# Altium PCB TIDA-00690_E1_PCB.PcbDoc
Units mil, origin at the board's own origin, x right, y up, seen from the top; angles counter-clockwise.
Board outline 2500 x 1700 mil, 2 copper layers (Top Layer, Bottom Layer), stack 62 mil thick; 46 components, 17 nets, 92 pads, 37 vias.
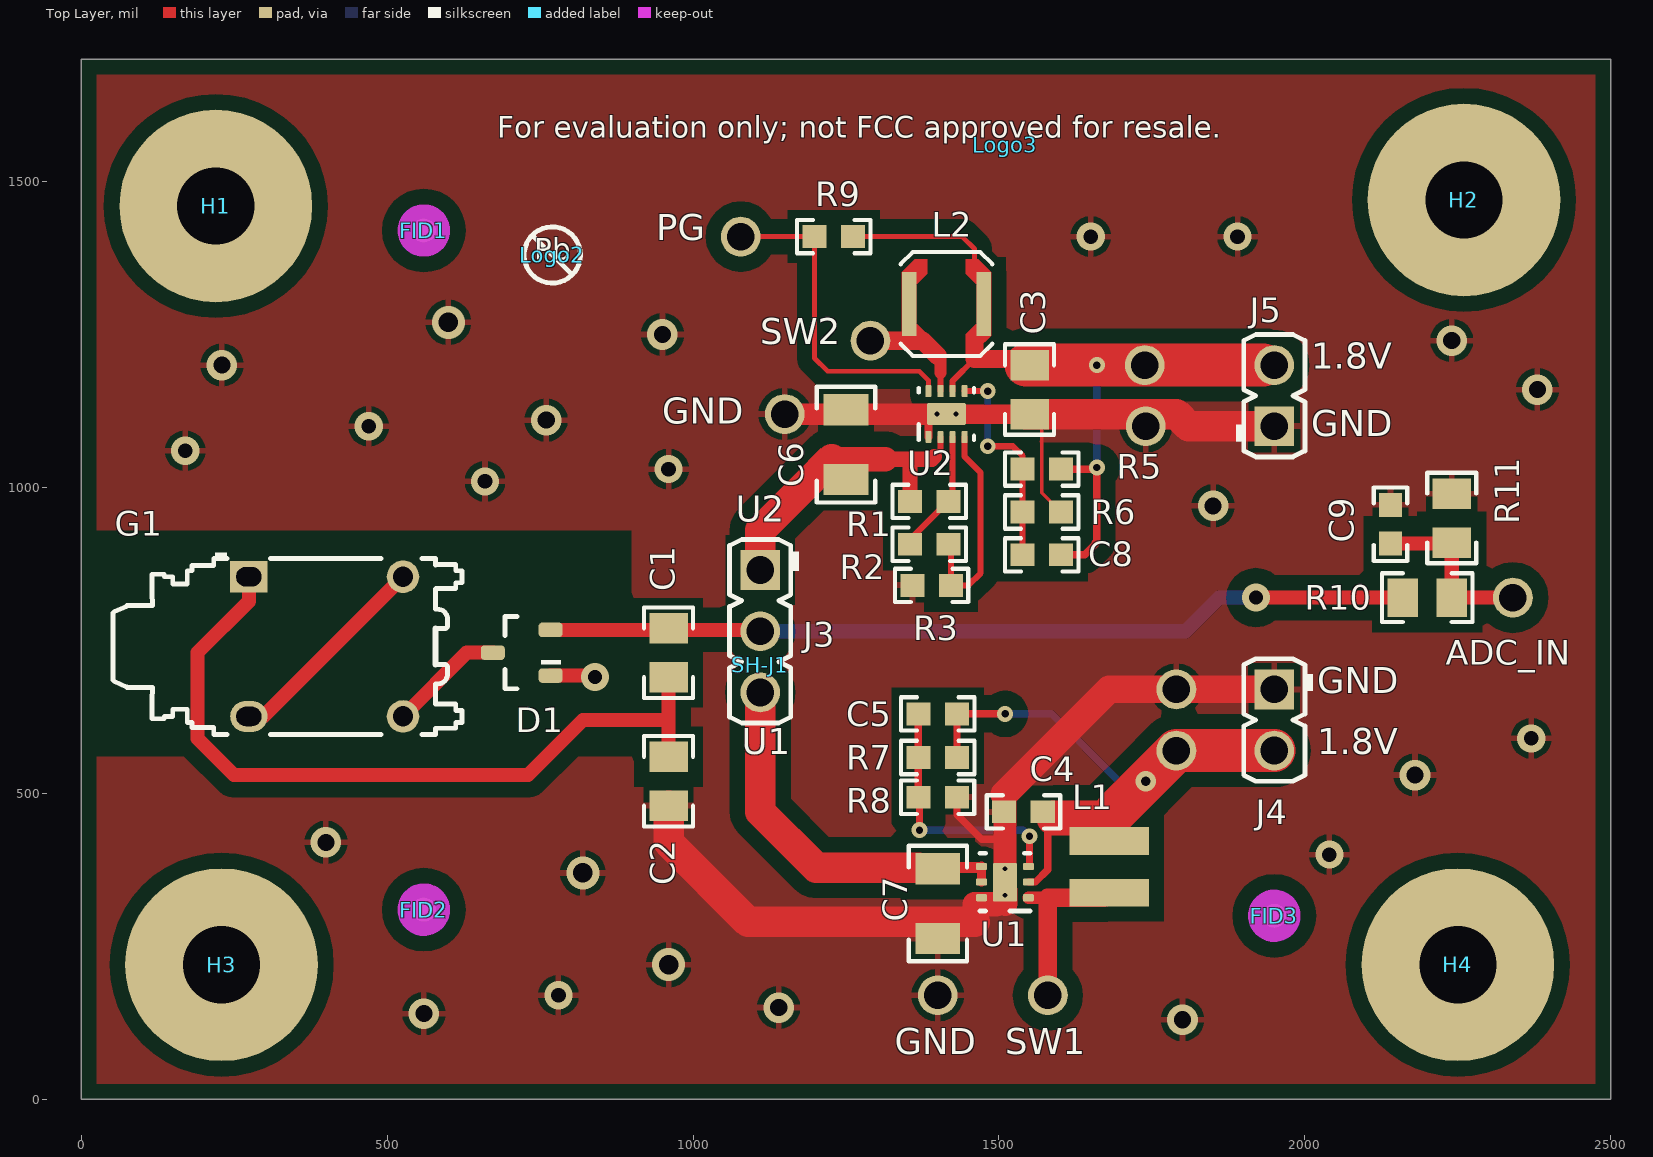
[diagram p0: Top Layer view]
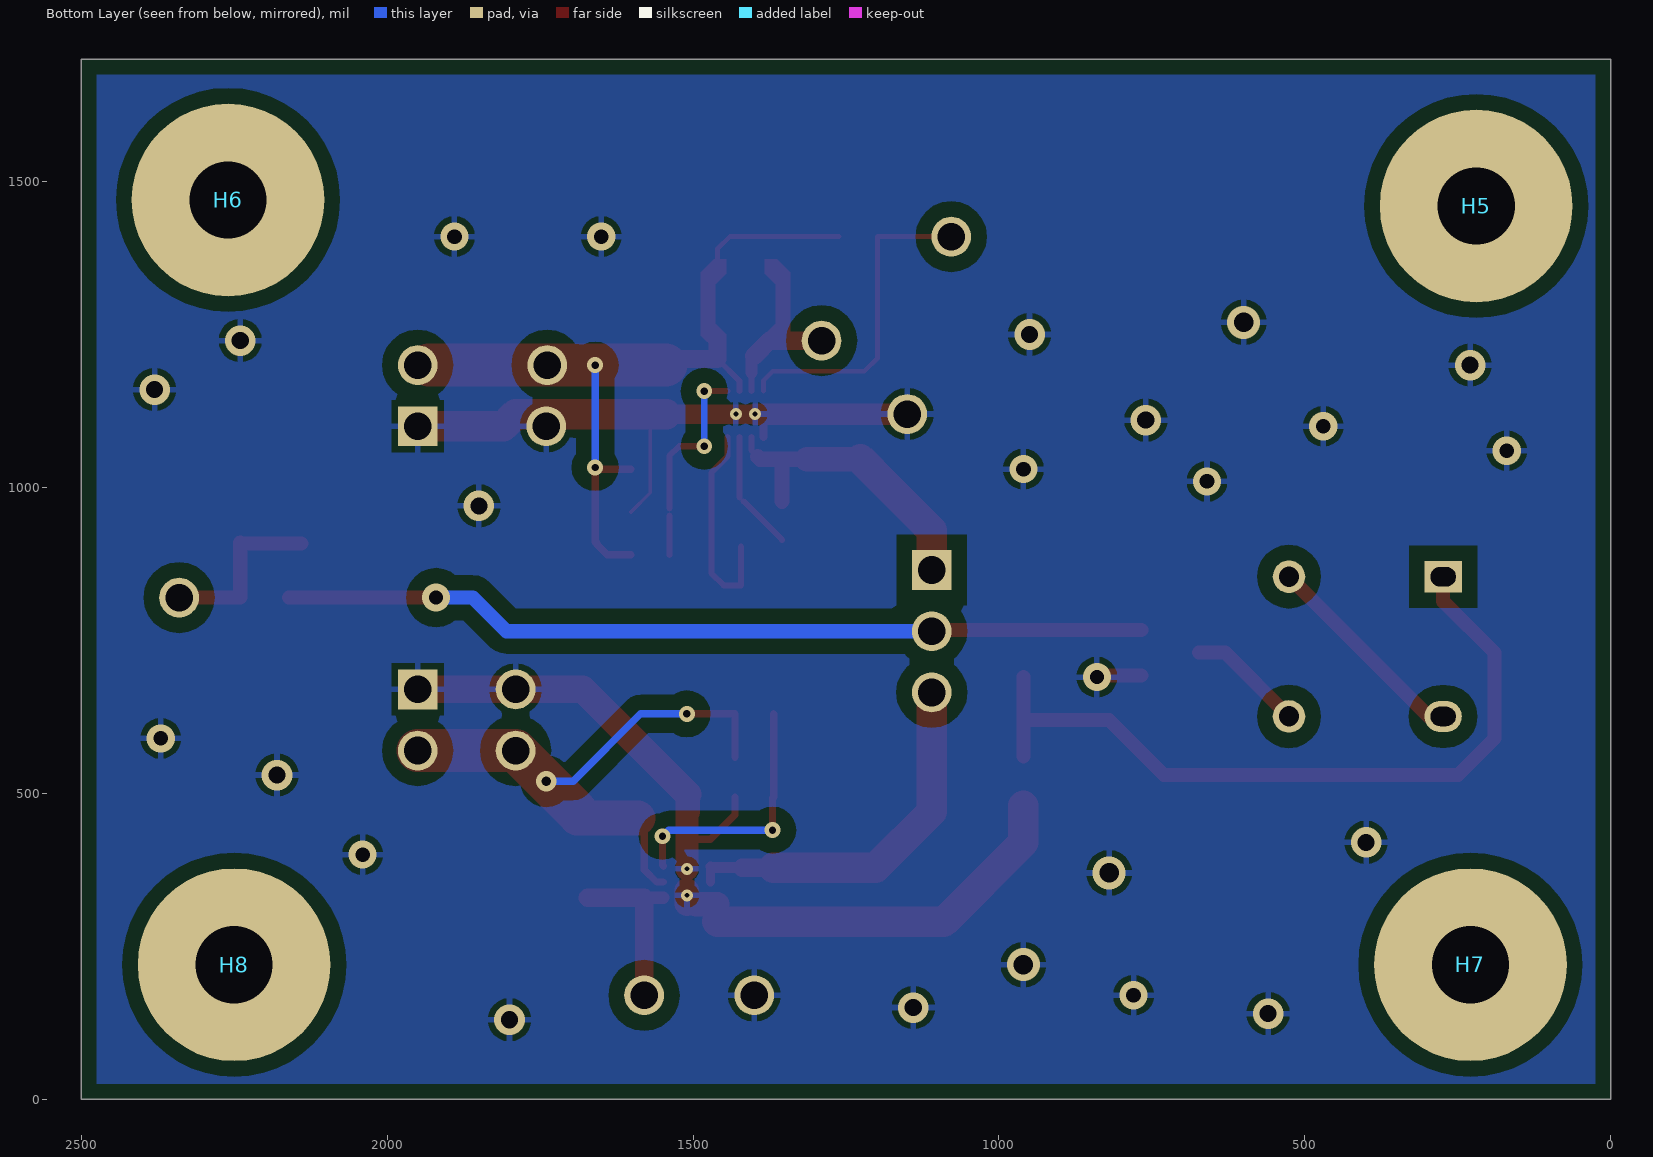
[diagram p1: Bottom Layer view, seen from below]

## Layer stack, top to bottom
Top Solder: solder mask 0.4, Solder Resist, Dk 3.5
Top Layer: signal copper 1.4
Dielectric1: core 59.2, FR-4, Dk 4.8
Bottom Layer: signal copper 1.4
Bottom Solder: solder mask 0.4, Solder Resist, Dk 3.5

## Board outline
0,0 2500,0 2500,1700 0,1700

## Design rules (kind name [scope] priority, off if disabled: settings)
AcuteAngle [All] p1: minimum=4.50000000000000E+0001 checktracksonly=FALSE
AssemblyTestPointUsage [All] p1: valid=2
BoardOutlineClearance BoardOutlineClearance_MountingHoles [OnCopper and InComponentClass('Mounting Holes')] p1: gap=40
BoardOutlineClearance BoardOutlineClearance_Poly [OnCopper and IsPoly] p2: gap=25
BoardOutlineClearance [OnCopper and Not InComponentClass('Logo') and not InComponentClass('FiducialMark') and not InRegion(1000,500,4000,800) and not InPoly] p3: gap=75
Clearance Clearance_Keepouts [((IsTrack Or IsArc) And Not InPoly) And IsFree and IsKeepOut vs ((IsTrack Or IsArc) And Not InPoly) And IsFree and IsKeepOut] p1: gap=0
Clearance Clearance_Poly [InPolygon] p2: gap=25
Clearance [All] p3: gap=7.87
ComponentClearance ComponentClearance_MountingHoles_FiducialMarks [InComponentClass('Mounting Holes') vs InComponentClass('FiducialMark')] p1: gap=50 collisioncheckmode=3 verticalgap=10 showdistances=FALSE
ComponentClearance ComponentClearance_Shunt [InComponentClass('Header') vs InComponentClass('Shunt')] p2: gap=0 collisioncheckmode=3 verticalgap=0 showdistances=FALSE
ComponentClearance ComponentClearance_Logo [InComponentClass('Logo')] p3: gap=50 collisioncheckmode=3 verticalgap=10 showdistances=FALSE
ComponentClearance ComponentClearance_ScrewToNut [(HasFootprint('NY PMS 440 0025 PH')) vs (HasFootprint('Keystone_1902C'))] p4: gap=5 collisioncheckmode=3 verticalgap=10 showdistances=FALSE
ComponentClearance ComponentClearance_MountingHoles [InComponentClass('Mounting Holes')] p5: gap=200 collisioncheckmode=3 verticalgap=100000 showdistances=FALSE
ComponentClearance ComponentClearance_SmallPassives [HasFootprint('0201*') or HasFootprint('0402*') or HasFootprint('0508') or HasFootprint('0603*') or HasFootprint('0612') or HasFootprint('0805*') or HasFootprint('0815*') or HasFootprint('0830*') or HasFootprint('1206*') or HasFootprint('1210*') or HasFootprint('1808*') or HasFootprint('1812*') or HasFootprint('1825*') or HasFootprint('2010*') or HasFootprint('2220*') or HasFootprint('2225*') or HasFootprint('2512*') or HasFootprint('2728*') or HasFootprint('3518*') vs HasFootprint('0201*') or HasFootprint('0402*') or HasFootprint('0508') or HasFootprint('0603*') or HasFootprint('0612') or HasFootprint('0805*') or HasFootprint('0815*') or HasFootprint('0830*') or HasFootprint('1206*') or HasFootprint('1210*') or HasFootprint('1808*') or HasFootprint('1812*') or HasFootprint('1825*') or HasFootprint('2010*') or HasFootprint('2220*') or HasFootprint('2225*') or HasFootprint('2512*') or HasFootprint('2728*') or HasFootprint('3518*')] p6: gap=14.96 collisioncheckmode=3 verticalgap=10 showdistances=FALSE
ComponentClearance ComponentClearance_THtoSMT [IsThruComponent vs IsSMTComponent] p7: gap=40 collisioncheckmode=3 verticalgap=30 showdistances=FALSE
ComponentClearance ComponentClearance_THtoTH [IsThruComponent vs IsThruComponent] p8: gap=30 collisioncheckmode=3 verticalgap=30 showdistances=FALSE
ComponentClearance [All] p9: gap=30 collisioncheckmode=3 verticalgap=10 showdistances=FALSE
DiffPairsRouting [All] p1: maxlimit=100 minlimit=10 mostfreqgap=10 toplayer_minwidth=15 toplayer_maxwidth=15 toplayer_prefwidth=15 bottomlayer_minwidth=15 bottomlayer_maxwidth=15 bottomlayer_prefwidth=15 maxuncoupledlength=1000
FabricationTestPointUsage TestPointUsage [All] p1: valid=2 allowmultiple=FALSE
FabricationTestpoint Testpoint [All] p1: side=3 testpointundercomponent=TRUE minsize=40 maxsize=100 preferedsize=60 minholesize=0 maxholesize=40 preferedholesize=32 testpointgrid=1 allowsidetop=TRUE allowsidebottom=TRUE usegrid=TRUE gridtolerance=0.01
FanoutControl Fanout_LCC [IsLCC] p1: bgadir=Out bgaviamode=Centered fanoutstyle=Auto fanoutdirection=Alternating viagrid=1 // Fanout_LCC (Default Rule)
FanoutControl Fanout_BGA [IsBGA] p2: bgadir=Out bgaviamode=Centered fanoutstyle=Auto fanoutdirection=Alternating viagrid=1 // Fanout_BGA (Default Rule)
FanoutControl Fanout_Default [All] p4: bgadir=Out bgaviamode=Centered fanoutstyle=Auto fanoutdirection=Alternating viagrid=1 // Fanout_Default (Default Rule)
FanoutControl Fanout_Small [(CompPinCount < 5)] p5: bgadir=Out bgaviamode=Centered fanoutstyle=Auto fanoutdirection=OutThenIn viagrid=1 // Fanout_Small (Default Rule)
HoleSize [All] p1: absolutevalues=TRUE maxlimit=251 minlimit=7.87 maxpercent=80.000 minpercent=20.000
MinimumAnnularRing MinimumAnnularRing_ThermalPadVias [IsVia and InAnyComponent] p1: minimumring=5.91
MinimumAnnularRing [All] p2: minimumring=6
MinimumSolderMaskSliver MinimumSolderMaskSliver_Logo [InComponentClass('Logo') vs InComponentClass('Logo')] p1: minsoldermaskwidth=0.7
MinimumSolderMaskSliver [All] p2: minsoldermaskwidth=3.94
PlaneConnect [All] p1: planeconnectstyle=Relief reliefexpansion=10 reliefentries=4 reliefconductorwidth=10 reliefairgap=10
PolygonConnect [All] p1: connectstyle=Relief reliefconductorwidth=10 reliefentries=4 polygonreliefangle="90 Angle" airgapwidth=10
RoutingVias ThermalPadVias [IsVia and InAnyComponent] p1: holewidth=7.87 width=19.68 viastyle="Through Hole" minholewidth=7.87 minwidth=19.68 maxholewidth=12.99 maxwidth=23.62
RoutingVias [All] p2: holewidth=16 width=34 viastyle="Through Hole" minholewidth=7.87 minwidth=26 maxholewidth=40 maxwidth=65
SilkToBoardRegionClearance [Not ((IsComment or IsDesignator) And (Hide <> 'False')) and not InRegion(1000,500,4000,800)] p1:
SilkToSilkClearance SilkToSilkClearance_Pb-FreeLogo [(HasFootprint('Pb-Free_Overlay_Medium') OR HasFootprint('Pb-Free_Overlay_Small')) vs (HasFootprint('Pb-Free_Overlay_Medium') OR HasFootprint('Pb-Free_Overlay_Small'))] p1: silktosilkclearance=0
SilkToSilkClearance [All] p2: silktosilkclearance=4
SilkToSolderMaskClearance SilkToComponentPadClearance [IsPad and InAnycomponent] p1: minsilkscreentomaskgap=2 clearancetoexposedcopper=TRUE
SilkToSolderMaskClearance "Silk to Solder Mask Opening" [All] p2: minsilkscreentomaskgap=3.8 clearancetoexposedcopper=FALSE
SolderMaskExpansion [All] p1: expansion=1.97
Width [All] p1: maxlimit=100 minlimit=6 preferedwidth=10 checkconnectedcopper=TRUE
15 further rules are at their usual default settings.

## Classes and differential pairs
component class TIDA-00690_E1_BlankSheet: ADC_IN C1 C2 C3 C4 C5 C6 C7 C8 C9 D1 G1 J3 J4 J5 L1 L2 R1 R2 R3 R5 R6 R7 R8 R9 R10 R11 SH-J1 U1 U2
component class Shunt: SH-J1
component class Header: J3 J4 J5
component class "Mounting Holes": H1 H2 H3 H4
component class TIDA-00690_E1_EVM_Hardware: FID1 FID2 FID3 H1 H2 H3 H4 H5 H6 H7 H8 Logo2 Logo3 ZZ2 ZZ3 ZZ4
component class FiducialMark: FID1 FID2 FID3
component class AssemblyNote: ZZ2 ZZ3 ZZ4

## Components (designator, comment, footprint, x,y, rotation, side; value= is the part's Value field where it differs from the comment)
ADC_IN "TESTPOINT" TP_H045P075 2340,820 r90 top
C1 "GRM21BR61E106MA73" 0805_HV 960,730 r270 top
C2 "GRM21BR61E106MA73" 0805_HV 960,520 r270 top
C3 "GRM21BR61C106KE15L" 0805_HV 1550,1160 r270 top
C4 "GRM188R60J475KE19D" 0603 1540,470 r180 top
C5 "GRM1885C1H220JA01D" 0603 1400,630 r180 top
C6 "GRM3195C1H102JA01D" 1206 1250,1070 r90 top
C7 "GRM3195C1H102JA01D" 1206 1400,320 r270 top
C8 "GRM1885C1H220JA01D" 0603 1570,890 r180 top
C9 "GRM188R71E104KA01D" 0603 2140,940 r90 top
D1 "DB3X316F0L" SOT-23 720,730 r180 top
FID1 "Fiducial" Fiducial10-20 560,1420 r0 top
FID2 "Fiducial" Fiducial10-20 560,310 r0 top
FID3 "Fiducial" Fiducial10-20 1950,300 r0 top
G1 "AFIG-0007" Cherry_AFIG-0007 400,740 r0 top
H1 "NY PMS 440 0025 PH" "NY PMS 440 0025 PH" 220,1460 r0 top locked
H2 "NY PMS 440 0025 PH" "NY PMS 440 0025 PH" 2260,1470 r0 top locked
H3 "NY PMS 440 0025 PH" "NY PMS 440 0025 PH" 229.47,220 r0 top locked
H4 "NY PMS 440 0025 PH" "NY PMS 440 0025 PH" 2250,220 r0 top locked
H5 "1902C" Keystone_1902C 220,1460 r180 bottom locked
H6 "1902C" Keystone_1902C 2260,1470 r180 bottom locked
H7 "1902C" Keystone_1902C 229.47,220 r180 bottom locked
H8 "1902C" Keystone_1902C 2250,220 r180 bottom locked
J3 "61300311121" WURTH_61300311121 1109.84,765.08 r270 top
J4 "61300211121" WURTH_61300211121 1950,620 r270 top
J5 "61300211121" WURTH_61300211121 1950,1150 r90 top
L1 "LQH3NPN220NG0" LQH3NP_G0 1680,380 r90 top
L2 "LPS3314-153MLB" LPS3314 1414.25,1300 r0 top
Logo2 "Pb-Free Symbol" Pb-Free_Overlay_Small 770,1380 r0 top
Logo3 "FCC disclaimer" FCC_disclaimer 1510,1560 r0 top
R1 "CRCW0603255KFKEA" 0603 1386,977.27 r180 top
R2 "CRCW0603200KFKEA" 0603 1386,907.27 r180 top
R3 "RC0603JR-0751KL" 0603 1390,840 r0 top
R5 "CRCW0603300KFKEA" 0603 1570,1030 r0 top
R6 "RC0603FR-07240KL" 0603 1570,960 r180 top
R7 "CRCW0603300KFKEA" 0603 1400,558.7 r0 top
R8 "RC0603FR-07240KL" 0603 1399.84,493.78 r180 top
R9 "CRCW0603100KJNEA" 0603 1230,1410 r0 top
R10 "CRCW08051M60JNEA" 0805_HV 2200,820 r180 top
R11 "CRCW08051M20JNEA" 0805_HV 2240,950 r270 top
SH-J1 "969102-0000-DA" SNT-100-BK-G 1110,710 r90 top
U1 "TPS62122DRVR" DRV0006A 1509.84,355.08 r180 top
U2 "TPS62125DSGR" DSG0008A 1414.25,1120 r90 top
ZZ2 "These assemblies are ESD sensitive, ESD precautions shall be observed." AssemblyNote 215,2539.11 r0 top
ZZ3 "These assemblies must be clean and free from flux and all contaminants. Use of no clean flux is not acceptable." AssemblyNote 215,2450.56 r0 top
ZZ4 "These assemblies must comply with workmanship standards IPC-A-610 Class 2, unless otherwise specified." AssemblyNote 215,2362 r0 top

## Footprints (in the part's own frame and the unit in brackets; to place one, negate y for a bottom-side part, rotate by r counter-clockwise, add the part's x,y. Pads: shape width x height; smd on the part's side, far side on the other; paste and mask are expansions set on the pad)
0603 [mm] "0603 from SM-752 data"
  rect 1x0.95 smd: 1(-0.8,0) 2(0.8,0)
  silkscreen extent -1.52,-0.69 1.52,0.69, body extent -0.87,-0.47 0.87,0.47, height 1
0805_HV [mil] "0805 with 30mil clearance between pads"
  rect 50x63 smd: 1(-40,0) 2(40,0)
  silkscreen extent -74,-40 74,40, body extent -43,-29 43,29, height 57
1206 [mm] "1206 from SM-752 data"
  rect 1.3x1.85 smd: 1(-1.45,0) 2(1.45,0)
  silkscreen extent -2.4,-1.21 2.4,1.21, body extent -1.7,-0.9 1.7,0.9, height 1.35
AssemblyNote [mil] "Assembly Note"
Cherry_AFIG-0007 [mm] "AC generator, Through-hole mount"
  rect 1.55x1.3 hole 0.8 slot 1.05 at 0 deg: 1(-3.2,2.9)
  oval 1.55x1.3 hole 0.8 slot 1.05 at 0 deg: 2(-3.2,-2.9)
  round 1.35 hole 0.85: 3(3.2,-2.9) 4(3.2,2.9)
  silkscreen extent -8.84,-3.65 5.65,3.9, body extent -8.84,-3.65 5.64,3.65, height 18.51
DRV0006A [mm] "SON, 6-Leads, Body 2x2mm, Pitch 0.65mm, Thermal Pad 1.6x1mm, TI Recommended"
  rrect33% 0.45x0.3 smd: 1(-0.975,0.65) 2(-0.975,0) 3(-0.975,-0.65) 4(0.975,-0.65) 5(0.975,0) 6(0.975,0.65)
  rrect14% 1x0.7 on Top Paste: 7(0,0.45) 7(0,-0.45)
  rrect10% 1x1.6 smd paste-0.5: 7(0,0)
  silkscreen extent -1.05,-1.2 1.05,1.2, body extent -1.05,-1.05 1.05,1.05, height 0.81
DSG0008A [mm] "SON, 8-Leads, Body 2x2mm, Pitch 0.5mm, Thermal Pad 1.6x0.9mm, TI Recommended"
  rrect40% 0.5x0.25 smd: 1(-0.95,0.75) 2(-0.95,0.25) 3(-0.95,-0.25) 4(-0.95,-0.75) 5(0.95,-0.75) 6(0.95,-0.25) 7(0.95,0.25) 8(0.95,0.75)
  rrect11% 0.9x1.6 smd paste-0.45: 9(0,0)
  silkscreen extent -1.07,-1.15 1.07,1.15, body extent -1.05,-1.05 1.05,1.05, height 0.8
FCC_disclaimer [mil]
Fiducial10-20 [mm]
  round 1 smd mask+0.5: 1(0,0)
  Top Layer keep-out circle w1.178: c0,0 r0.5
Keystone_1902C [mil] "Hex Standoff, 4-40 threaded, nylon"
  body extent -145,-126 146,126, height 501
LPS3314 [mm] "Coilcraft recommended land pattern, Document 541-2 Revised 08/05/09"
  rect 0.6x2.65 smd: 1(-1.55,0) 2(1.55,0)
  Top Layer region: 0.8,-1.85 0.8,-1.25 1.25,-0.8 1.25,0.8 0.8,1.25 0.8,1.85 1.325,1.85 1.85,1.325 1.85,-1.325 1.325,-1.85
  Top Layer region: -1.325,-1.85 -1.85,-1.325 -1.85,1.325 -1.325,1.85 -0.8,1.85 -0.8,1.25 -1.25,0.8 -1.25,-0.8 -0.8,-1.25 -0.8,-1.85
  silkscreen extent -1.91,-2.16 1.91,2.16, body extent -1.7,-1.7 1.7,1.7, height 1.42
LQH3NP_G0 [mm] "MURATA"
  rect 1.15x3.3 smd: 1(-1.075,0) 2(1.075,0)
  body extent -1.6,-1.6 1.6,1.6, height 1.01
"NY PMS 440 0025 PH" [mm] "4-40 nylon screw and mounting hole"
  round 8 hole 3.2: 1(0,0)
  body extent -3.3,-3.3 3.3,3.3, height 2.69
Pb-Free_Overlay_Small [mil]
  silkscreen extent -46,-46 46,46
SNT-100-BK-G [mil] "Samtec STEP model"
  round 1 on Mech3: 0(0,0)
  body extent -100,-50 100,50, height 344
SOT-23 [mm] "SOT23, 3-Leads, Body 2.9x1.3mm, Pitch 0.95mm, Lead Span 2.5mm, IPC Medium Density"
  rrect50% 1x0.6 smd: 1(-1.2,0.95) 2(-1.2,-0.95) 3(1.2,0)
  silkscreen extent -1.63,-1.5 0.7,1.5, body extent -1.16,-1.45 1.21,1.45, height 1
TP_H045P075 [mil] "TP_H0.45P0.75"
  round 65 hole 45: 1(0,0)
WURTH_61300211121 [mm] "Header, 2.54mm, 2x1, TH"
  rect 1.65x1.65 hole 1.15: 1(-1.27,0)
  round 1.65 hole 1.15: 2(1.27,0)
  silkscreen extent -2.54,-1.27 2.54,1.6, body extent -2.54,-1.27 2.54,1.27, height 8.54
WURTH_61300311121 [mm] "Header, 2.54mm, 3x1, TH"
  rect 1.65x1.65 hole 1.15: 1(-2.54,0)
  round 1.65 hole 1.15: 2(0,0) 3(2.54,0)
  silkscreen extent -3.81,-1.27 3.81,1.6, body extent -3.81,-1.27 3.81,1.27, height 8.54

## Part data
ADC_IN: library part TP_H0.45P0.75, "Testpoint"
C1 C2: "CAP, CERM, 10 µF, 25 V, +/- 20%, X5R, 0805"
C3: "CAP, CERM, 10 µF, 16 V, +/- 10%, X5R, 0805"
C4: "CAP, CERM, 4.7 µF, 6.3 V, +/- 10%, X5R, 0603"
C5 C8: "CAP, CERM, 22 pF, 50 V, +/- 5%, C0G/NP0, 0603"
C6 C7: "CAP, CERM, 1000 pF, 50 V, +/- 5%, C0G/NP0, 1206"
C9: "CAP, CERM, 0.1 µF, 25 V, +/- 10%, X7R, 0603"
D1: "Diode, Schottky, 30 V, 0.1 A, SOT-23"
FID1 FID2 FID3: "Fiducial mark.  There is nothing to buy or mount."
G1: "AC generator, Through-hole mount"
H1 H2 H3 H4: "Machine Screw, Round, #4-40 x 1/4, Nylon, Philips panhead"
H5 H6 H7 H8: "Standoff, Hex, 0.5\"L #4-40 Nylon"
J3: "Header, 2.54 mm, 3x1, Gold, TH"
J4 J5: "Header, 2.54 mm, 2x1, Gold, TH"
L1: "Inductor, Wirewound, Ferrite, 22 µH, 0.34 A, 1.1 ohm, SMD"
L2: "Inductor, Shielded Drum Core, Ferrite, 15 µH, 0.59 A, 0.44 ohm, SMD"
Logo2: library part Pb-Free
Logo3: library part FCC_disclaimer, "FCC_disclaimer"
R1: "RES, 255 k, 1%, 0.1 W, 0603"
R2: "RES, 200 k, 1%, 0.1 W, 0603"
R3: "RES, 51 k, 5%, 0.1 W, 0603"
R5 R7: "RES, 300 k, 1%, 0.1 W, 0603"
R6 R8: "RES, 240 k, 1%, 0.1 W, 0603"
R9: "RES, 100 k, 5%, 0.1 W, 0603"
R10: "RES, 1.6 M, 5%, 0.125 W, 0805"
R11: "RES, 1.2 M, 5%, 0.125 W, 0805"
SH-J1: "Shunt, 100mil, Gold plated, Black"
U1: "Buck Step Down Regulator with 2 to 15 V Input and 1.2 to 5.5 V Output, -40 to 85 degC, 6-Pin SON (DRV), Green (RoHS & no Sb/Br)"
U2: "3V-17V, 300mA Step Down Converter With Adjustable Enable Threshold And Hysteresis, DSG0008A"
ZZ2 ZZ3 ZZ4: library part AssemblyNote

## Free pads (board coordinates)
  round 65 hole 45: 3(1400,170) 4(1290,1240) 5(1150,1120) 6(1738.37,1200) 7(1740,1100) 8(1790,670) 9(1790,570) 10(1078,1410) 12(1580,170)

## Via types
v1: diameter 50, hole 28, Top Layer to Bottom Layer, 11 vias
v2: diameter 46, hole 24, Top Layer to Bottom Layer, 9 vias
v3: diameter 26, hole 12, Top Layer to Bottom Layer, 7 vias
v4: diameter 19.68, hole 7.87, Top Layer to Bottom Layer, 4 vias
v5: diameter 54, hole 32, Top Layer to Bottom Layer, 3 vias
v6: diameter 46, hole 23, Top Layer to Bottom Layer, 2 vias
v7: diameter 34, hole 16, Top Layer to Bottom Layer, 1 vias

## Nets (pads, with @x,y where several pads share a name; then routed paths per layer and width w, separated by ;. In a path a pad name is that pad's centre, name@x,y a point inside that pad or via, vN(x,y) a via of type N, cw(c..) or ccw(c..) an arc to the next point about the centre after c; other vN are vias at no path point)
GND: C2.2 C3.2 C4.2 C6.2 C7.2 C9.2 D1.1 J4.1 J5.1 pad.3 pad.5 pad.7 pad.8 R3.1 R6.1 R8.1 R11.1 U1.6 U1.7@1509.84,355.08 U2.1 U2.9 | length 2465
  Top Layer w6: C3.2@1570,1120 1570,991.5 R6.1
  Top Layer w12: R8.1 1431.34,465.08 1471.34,425.08 1509.84,425.08
  Top Layer w13: U2.1 U2.9@1384.72,1105.37
  Top Layer w23: D1.1 v6@837.4,692.6
  Top Layer w32: v4(1398.5,1120) U2.9 C3.2@1544.25,1120
  Top Layer w35: pad.5@1180,1120 v4(1398.5,1120)
  Top Layer w38: v4(1509.84,376.73) 1509.84,425.08 C4.2@1509.84,466.57
  Top Layer w40: 1460,319.12 1495.54,319.12 ; C4.2 1508.5,498.5 ; 1510,320 U1.7@1510,341.65
  Top Layer w45: 1508.5,498.5 1680,670 J4.1@1940,670
  Top Layer w50: C2.2 960,420 1090,290 1460,290 ; C3.2@1544.25,1120 1790,1120 1810,1100 J5.1@1955,1100
  other v1: 1800,130 560,140 1140,150 400,420 2180,530 1850,970 760,1110 2380,1160 230,1200 2240,1240 950,1250
  other v2: 780,170 2040,400 2370,590 660,1010 960,1030 170,1060 470,1100 1650,1410 1890,1410
  other v4: 1509.84,333.43 1430,1120
  other v5: 960,220 820,370 600,1270
  other v6: 840,690
NetADC_IN_1: ADC_IN.1 C9.1 R10.1 R11.2 | length 288.5
  Top Layer w23: C9.1 R11.2@2238.5,908.5 ; R11.2 R10.1 ADC_IN.1
NetC1_1: C1.1 D1.2 J3.2 R10.2 | length 1413.2
  Top Layer w23: D1.2 J3.2@1107.52,767.4 ; v6(1920,820) R10.2
  Bottom Layer w23: J3.2 1805.08,765.08 1860,820 v6(1920,820)
NetC1_2: C1.2 C2.1 G1.1 | length 1261.1
  Top Layer w23: G1.1 274.02,814.02 190,730 190,590 250,530 730,530 820,620 960,620 ; C2.1 960,620 ; C1.2 960,620
NetC5_2: C5.2 R7.1 R8.2 U1.3 | length 425
  Top Layer w12: C5.2 1368.35,629.84 R8.2 1370,492.13 v3(1370,440) ; U1.3 1550,382.44 v3(1550,430)
  Bottom Layer w12: v3(1370,440) 1540,440 v3(1550,430)
NetC8_2: C8.2 R5.1 R6.2 U2.5 | length 341.3
  Top Layer w10: U2.5 v3(1481.65,1157.4) ; v3(1481.65,1067.4) 1522.6,1067.4 1538.5,1051.5 R5.1 R6.2@1538.5,965.75 ; C8.2 R6.2@1538.5,954.25
  Bottom Layer w10: v3(1481.65,1067.4) v3(1481.65,1157.4)
NetD1_3: D1.3 G1.3 | length 189.9
  Top Layer w23: G1.3 630.16,730 D1.3
NetG1_2: G1.2 G1.4 | length 346.6
  Top Layer w23: G1.2 297.64,625.83 G1.4
NetL1_1: L1.1 pad.12 U1.1 | length 283.1
  Top Layer w20: U1.1 1580,329.49
  Top Layer w30: pad.12 1580,329.49 L1.1@1671.81,329.49
NetL2_1: L2.1 pad.4 U2.7 | length 171.6
  Top Layer w10: U2.7 1404.41,1185.59
  Top Layer w20: 1404.41,1187.51 1404.41,1210.59
  Top Layer w30: pad.4 1375,1240 1400,1215
NetR1_1: R1.1 R2.2 U2.3 | length 187.8
  Top Layer w10: R2.2@1354.5,914.27 R1.1 ; R1.1@1424.09,983.86 U2.3
NetR2_1: R2.1 R3.2 U2.4 | length 353.5
  Top Layer w10: R2.1@1421.5,903.27 R3.2 1450,840 1470,860 1470,1024.25 1443.78,1050.47 U2.4
NetR9_1: pad.10 R9.1 U2.8 | length 538.1
  Top Layer w8: pad.10 R9.1 1198.5,1211.5 1220,1190 1370,1190 1384.72,1175.28 U2.8
VIN1: C7.1 J3.3 U1.4 U1.5 | length 620.8
  Top Layer w14: U1.5 U1.4
  Top Layer w16: U1.4@1469.49,378.7 U1.4
  Top Layer w18: C7.1@1419.84,378.7 U1.4@1469.49,378.7
  Top Layer w30: C7.1@1368.7,378.7 C7.1@1419.84,378.7
  Top Layer w50: J3.3 1109.84,470.16 1201.3,378.7 C7.1@1368.7,378.7
VIN2: C6.1 J3.1 R1.2 U2.2 | length 502.8
  Top Layer w10: 1394.25,1050 1404.41,1060.16 U2.2
  Top Layer w25: 1314.25,1046.38 1390.63,1046.38 1394.25,1050 ; R1.2 1354.5,1044.32
  Top Layer w40: 1226.38,1046.38 1314.25,1046.38
  Top Layer w50: J3.1 1109.84,929.84 1185.08,1005.08 1226.38,1046.38
VOUT1: C4.1 C5.1 J4.2 L1.2 pad.9 R7.2 U1.2 | length 948.3
  Top Layer w12: R7.2@1431.34,558.7 1431.34,630 v3(1510,630) ; U1.2 1559.84,355.08 1579.84,375.08 C4.1@1579.84,456.57
  Top Layer w57: C4.1@1590,460 1690,460
  Top Layer w70: 1690,470 v7(1740,520) pad.9 J4.2
  Bottom Layer w12: v3(1510,630) 1585.78,630 1695.78,520 v7(1740,520)
VOUT2: C3.1 C8.1 J5.2 L2.2 pad.6 R5.2 R9.2 U2.6 | length 1217.4
  Top Layer w8: R9.2 1440,1410 1460,1390 1460,1360
  Top Layer w10: U2.6 1424.09,1174.09 1460,1210
  Top Layer w12: C8.1 1640,890 1657.32,907.32 1657.32,910 ; R5.2 v3@1657.32,1030 ; 1660,910 v3(1660,1032.68)
  Top Layer w30: 1460,1235 1460,1210 1534.25,1210 C3.1@1544.25,1200
  Top Layer w70: C3.1@1544.25,1200 J5.2@1932.49,1200
  Bottom Layer w12: v3(1660,1032.68) v3(1660,1200)
pads on no net: FID1.1 FID2.1 FID3.1 H1.1 H2.1 H3.1 H4.1 SH-J1.0 U1.7@1509.84,337.36 U1.7@1509.84,372.8

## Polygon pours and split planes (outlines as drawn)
GND on Bottom Layer "GND" (solid, remove dead copper, pour order 0): 0,0 2500,0 2500,1680 0,1680
GND on Top Layer "GND" (solid, remove dead copper, pour order 2): 0,0 2500,0 2500,1680 0,1680

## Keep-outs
Keep-Out Layer:
  text ".Layer_Name" at 577,-858.49 h60

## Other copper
Top Layer:
  pour cut-out: 10,930 900,930 900,560 10,560
  text ".Layer_Name" at 577,-858.49 h60
Bottom Layer:
  text ".Layer_Name" at 577,-858.49 h60

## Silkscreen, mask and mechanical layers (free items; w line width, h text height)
Top Overlay:
  text "PG" at 940,1390 h72.83
  text "SW2" at 1110,1220 h72.83
  text "1.8V" at 2010,1180 h72.83
  text "GND" at 950,1090 h72.83
  text "GND" at 2010,1070 h72.83
  text "U2" at 1070,930 h72.83
  text "GND" at 2020,650 h72.83
  text "U1" at 1080,550 h72.83
  text "1.8V" at 2020,550 h72.83
  text "GND" at 1330,60 h72.83
  text "SW1" at 1510,60 h72.83
  text ".Layer_Name" at 577,-858.49 h60
Bottom Overlay:
  text ".Layer_Name" at 577,-858.49 h60
Top Paste:
  text ".Layer_Name" at 577,-858.49 h60
Bottom Paste:
  text ".Layer_Name" at 577,-858.49 h60
Top Solder:
  text ".Layer_Name" at 577,-858.49 h60
  text ".Layer_Name" at 577,-858.49 h60
Bottom Solder:
  text ".Layer_Name" at 577,-858.49 h60
Drill Guide:
  text ".Layer_Name" at 577,-858.49 h60
M1 Board Outline:
  the board outline again, w10
  text ".Layer_Name" at 577,-858.49 h60
M2 Board Dimensions:
  rectangle: 0,-275 125,-150
  rectangle: 125,-400 500,-275
  lines w7: 0,-275 1000,-275 ; 125,-400 125,-150 ; 250,-400 250,-150 ; 500,-400 500,-150 ; 750,-400 750,-150 ; 0,-400 1000,-400 1000,-150 0,-150 0,-400
  text ".Layer_Name" at 577,-858.49 h60
M3 3D STEP Top:
  text ".Layer_Name" at 577,-858.49 h60
M4 3D STEP Bottom:
  text ".Layer_Name" at 577,-858.49 h60
M5 Assembly Top:
  lines w10: -292,-930.17 6308,-930.17 ; -292,-726.83 6310,-726.83 ; -292,-523.5 -292,-1133.5 3713,-1133.5 6310,-1133.5 6310,-523.5 -291.5,-523.5 -291.5,-1133.5 1284,-1133.5 ; 2173,-1133.5 2173,-523.5 ; 3440,-726.83 3440,-523.5 ; 4280,-726.83 4280,-523.5 ; 4902,-1140 4902,-937.17
  text "COMPONENTS MARKED 'DNP' SHOULD NOT BE POPULATED." at 1153.5,-318.5 h60
  text "ASSEMBLY VARIANT:" at 1153,-434 h60
  text ".VariantName" at 2189,-434 h60
  text "PCB VIEWED FROM TOP SIDE" at -228.5,-655.67 h60
  text "BOARD #:" at 2248,-655.67 h60
  text ".PRJ_Number" at 2793.5,-655.67 h60
  text "REV:" at 3638,-655.67 h60
  text ".PCB_Rev" at 3929.5,-655.67 h60
  text "SVN REV:" at 4476,-655.67 h60
  text ".VersionControl_RevNumber" at 4982,-655.67 h60
  text "TID #:" at 2248,-859 h60
  text ".TID" at 2793.5,-859 h60
  text "PLOT NAME =" at -228.5,-1064.34 h60
  text ".plot_File_Name" at 577,-1064.34 h60
  text "GENERATED    :" at 2250,-1064.34 h60
  text ".Print_Date" at 3119.5,-1064.34 h60
  text ".Print_Time" at 3848.5,-1064.34 h60
  text "TEXAS INSTRUMENTS" at 5113,-1064.34 h60
M6 Assembly Bottom:
  lines w10: -292.5,-727.33 6309.5,-727.33 ; -290.5,-930.67 6309.5,-930.67 ; 1115.5,-1140.5 1115.5,-937.67 ; 1737.5,-727.33 1737.5,-524 ; 2577.5,-727.33 2577.5,-524 ; 3844.5,-1134 3844.5,-524 ; 4733.5,-1134 6309,-1134 6309,-524 -292.5,-524 -292.5,-1134 2304.5,-1134 6309.5,-1134 6309.5,-524
  text "COMPONENTS MARKED 'DNP' SHOULD NOT BE POPULATED." at 6102,-318 h60
  text ".VariantName" at 5058,-434 h60
  text "ASSEMBLY VARIANT:" at 6097,-434 h60
  text ".VersionControl_RevNumber" at 1035.5,-656.17 h60
  text "SVN REV:" at 1541.5,-656.17 h60
  text ".PCB_Rev" at 2088,-656.17 h60
  text "REV:" at 2379.5,-656.17 h60
  text ".PRJ_Number" at 3224,-656.17 h60
  text "BOARD #:" at 3769.5,-656.17 h60
  text "PCB VIEWED FROM BOTTOM SIDE" at 6246,-656.17 h60
  text ".TID" at 3224,-859.5 h60
  text "TID #:" at 3769.5,-859.5 h60
  text "TEXAS INSTRUMENTS" at 904.5,-1064.84 h60
  text ".Print_Time" at 2169,-1064.84 h60
  text ".Print_Date" at 2898,-1064.84 h60
  text "GENERATED    :" at 3767.5,-1064.84 h60
  text ".plot_File_Name" at 5440.5,-1064.84 h60
  text "PLOT NAME =" at 6246,-1064.84 h60
M9 Title Sheet:
  drawing of 57 lines, arcs and shapes, not listed
  text "1" at 739.84,8036.5 h70
  text "2" at 3235.5,8036.5 h70
  text "3" at 5724.84,8036.5 h70
  text "4" at 8231.51,8036.5 h70
  text "5" at 10730.5,8036.5 h70
  text "6" at 13235.5,8036.5 h70
  text "A" at -416.5,6893.5 h70
  text "A" at 14383.5,6893.5 h70
  text "B" at -416.5,4513.5 h70
  text "B" at 14383.5,4513.5 h70
  text "C" at -416.5,2138.5 h70
  text "C" at 14383.5,2138.5 h70
  text "PROJECT TITLE:" at 11343.5,277.5 h45
  text ".PRJ_Title" at 11393.5,144.17 h70
  text "DESIGNED FOR:" at 11343.5,-23.5 h45
  text ".PRJ_Customer" at 11393.5,-163.5 h70
  text "D" at -416.5,-231.5 h70
  text "D" at 14383.5,-231.5 h70
  text "FILE NAME:" at 11343.5,-323.5 h45
  text ".PCB_File_Name_No_Path" at 11393.5,-443.5 h70
  text "Texas Instruments (TI) and/or its licensors do not warrant the accuracy or completeness of this specification" at 6374,-605.34 h45
  text "ENGINEER:" at 11343.5,-613.5 h45
  text "LAYOUT BY:" at 12848.5,-613.5 h45
  text "or any information contained therein. TI and/or its licensors do not warrant that this design will meet" at 6329.01,-718 h45
  text ".PRJ_Engineer" at 11393.5,-768.49 h70
  text ".PCB_Layout" at 12899,-768.49 h70
  text "the specifications, will be suitable for your application or fit for any particular purpose, or will operate in" at 6329.01,-830.67 h45
  text ".Layer_Name" at 577,-858.49 h60
  text "ALTIUM DESIGNER VERSION:" at 12848.5,-923.5 h45
  text "an implementation. TI and/or its licensors do not warrant that the design is production worthy. You should" at 6329.01,-943.33 h45
  text "completely validate and test your design implementation to confirm the system functionality for your application." at 6374,-1056 h45
  text ".print_Scale" at 11393.5,-1056.83 h70
  text ".Application_BuildNumber" at 12899,-1056.83 h70
  text "1" at 739.84,-1263.5 h70
  text "2" at 3235.5,-1263.5 h70
  text "3" at 5724.84,-1263.5 h70
  text "4" at 8231.51,-1263.5 h70
  text "5" at 10730.5,-1263.5 h70
  text "6" at 13235.5,-1263.5 h70
M10 Fab Notes:
  drawing of 173 lines, arcs and shapes, not listed
  text "DESIGN INFORMATION" at 12378.02,6201 h60
  text "MIN. TRACK WIDTH:" at 11733.46,6021 h60
  text "8" at 12829.7,6021 h60
  text "MIL" at 12984.46,6021 h60
  text "MIN. CLEARANCE:" at 11733.46,5889 h60
  text "0.2" at 12769.7,5889 h60
  text "mm" at 12984.46,5889 h60
  text "MIN. VIA PAD SIZE:" at 11733.46,5757 h60
  text "24" at 12799.71,5757 h60
  text "MIL" at 12984.46,5757 h60
  text "0.05mm (2MIL)" at 12428.46,5615.29 h60
  text "MINIMUM ANNULAR RING" at 11404.23,5611 h60
  text "EXTERNAL" at 13136.46,5611 h60
  text "PER" at 11604.23,5493 h60
  text "IPC-D-275 CLASS 2 LEVEL C" at 11824.23,5493 h60
  text "MIL, HOLES" at 13312.46,5380.71 h60
  text "+/-" at 12920,5380 h60
  text "+/-" at 13774,5380 h60
  text "REGISTRATION TOLERANCES:" at 11404.23,5375 h60
  text "METAL" at 12604,5375 h60
  text "5" at 13180.2,5375 h60
  text "3" at 14013.2,5375 h60
  text "MIL" at 14129.46,5375 h60
  text "+/-" at 13774,5262 h60
  text "HOLE SIZE TOLERANCE (UNLESS OTHERWISE SPECIFIED):" at 11404.23,5257 h60
  text "3" at 14013.2,5257 h60
  text "MIL" at 14129.46,5257 h60
  text "MATERIAL:" at 11329.46,5047.54 h60
  text "FR-4 High Tg" at 12315.9,4907.21 h60
  text "FR-408" at 11750.46,4898.64 h60
  text "OTHER" at 13238.46,4898.64 h60
  text "X" at 12161,4895 h60
  text "62 MIL (1.6mm) +/-10%" at 12070.56,4735.92 h60
  text "THICKNESS:" at 11404.23,4731.64 h60
  text "X" at 11942.4,4731.64 h60
  text "OTHER" at 13355.46,4731.64 h60
  text "TOLERANCE:" at 11404.23,4573.64 h60
  text "X" at 12243.53,4573.64 h60
  text "ANSI IPC-6012 TYPE 3 CLASS 2" at 12430.48,4573.64 h60
  text "OTHER +/-" at 12430.46,4417.64 h60
  text "BOW & TWIST:" at 11404.23,4260.64 h60
  text "X" at 12243.53,4260.64 h60
  text "ANSI IPC-6012 TYPE 3 CLASS 2" at 12430.48,4260.64 h60
  text "OTHER +/-" at 12430.46,4102.13 h60
  text "DRILLING:" at 11329.46,3963.64 h60
  text "REFERENCE:" at 11404.23,3846.64 h60
  text "X" at 12052.46,3846.64 h60
  text "AS SHOWN" at 12239.46,3846.64 h60
  text "X" at 12953.46,3846.64 h60
  text "NC_DRILL FILES" at 13090.46,3846.64 h60
  text "PTH COPPER THICKNESS:" at 11404.23,3688.64 h60
  text "X" at 12534.46,3688.64 h60
  text "20-30 um" at 12671.46,3688.64 h60
  text "OTHER" at 13388.46,3688.64 h60
  text "BOARD FINISH:" at 11329.46,3529.64 h60
  text "SILKSCREEN:" at 11484.68,3411.64 h60
  text "X" at 12433.46,3411.64 h60
  text "TOP" at 12559.46,3411.64 h60
  text "BOTTOM" at 13070.46,3411.64 h60
  text "SILKSCREEN COLOR:" at 11484.68,3244.64 h60
  text "X" at 12432.42,3244.64 h60
  text "WHITE" at 12559.46,3244.64 h60
  text "OTHER" at 13070.46,3244.64 h60
  text "X" at 12563.42,3085.44 h60
  text "GREEN" at 12690.46,3085.44 h60
  text "OTHER" at 13308.46,3085.44 h60
  text "SOLDER RESIST COLOR:" at 11484.68,3074.64 h60
  text "X" at 12563.42,2915.44 h60
  text "MATTE" at 12690.46,2915.44 h60
  text "SEMI-GLOSS" at 13308,2914.8 h60
  text "IMMERSION GOLD (ENIG)" at 12390.46,2726.92 h60
  text "ENEPIG" at 13728,2723.64 h60
  text "SURFACE FINISH:" at 11329.46,2722.64 h60
  text "X" at 12203.51,2722.64 h60
  text "IMM. TIN/SILVER OR EQUIV" at 11659,2565.64 h60
  text "OTHER" at 13090.46,2565.64 h60
  text "ARRAY/PANEL:" at 11329.46,2386.64 h60
  text "CUT AND TRIM PER M1 BOARD OUTLINE" at 12390.46,2382.35 h60
  text "N.C. ROUTE" at 12390.46,2230.64 h60
  text "X" at 13069.46,2230.64 h60
  text "V. SCORE" at 13256.46,2230.64 h60
  text "CERTIFICATION:" at 11329.46,2093.64 h60
  text "MATERIALS AND WORKMANSHIP FOR ALL PCBS" at 12054.46,2093.64 h60
  text "TO MEET OR EXCEED THE REQUIREMENTS OF:" at 12054.46,1995.64 h60
  text "X" at 11680.96,1859.13 h60
  text "ANSI IPC-A-600F CLASS ->" at 11819.96,1859.13 h60
  text "X" at 13459.02,1859.13 h60
  text "2" at 13577.96,1859.14 h60
  text "1" at 13262.96,1857.64 h60
  text "3" at 13931.96,1857.64 h60
  text "X" at 12495.02,1699.64 h60
  text "RoHS" at 12631.96,1699.64 h60
  text "OTHER" at 13276.36,1699.64 h60
  text "PER ORDER" at 13673.42,1699.64 h60
  text "ALL BOARDS MUST MEET OR EXCEED UL94-V0 REQUIREMENTS." at 11357,1534 h60
  text "PCB MUST BEAR THE UL94V-0 UL REGISTERED MATERIAL ID NUMBER" at 11357,1414 h60
  text "ADDITIONAL REQUIREMENTS:" at 11329.46,1240.64 h60
  text "MICROSECTION:" at 11404.23,1125.64 h60
  text "YES" at 12309.96,1125.64 h60
  text "REQUIRED" at 13171.46,969.49 h60
  text "BARE BOARD ELEC. TEST:" at 11404.23,966.64 h60
  text "NONE" at 12709.96,966.64 h60
  text "X" at 13044.46,966.64 h60
  text "PER ORDER" at 13763.46,966.64 h60
  text ".Layer_Name" at 577,-858.49 h60
M11 Gerber Information:
  lines w10: -292,-930.17 6308,-930.17 ; -292,-726.83 6310,-726.83 ; -292,-523.5 -292,-1133.5 3713,-1133.5 6310,-1133.5 6310,-523.5 -291.5,-523.5 -291.5,-1133.5 1284,-1133.5 ; 2173,-1133.5 2173,-523.5 ; 3440,-726.83 3440,-523.5 ; 4280,-726.83 4280,-523.5 ; 4902,-1140 4902,-937.17
  text "ALL ARTWORK VIEWED FROM TOP SIDE" at -228.5,-655.67 h60
  text "BOARD #:" at 2248,-655.67 h60
  text ".PRJ_Number" at 2793.5,-655.67 h60
  text "REV:" at 3638,-655.67 h60
  text ".PCB_Rev" at 3929.5,-655.67 h60
  text "SVN REV:" at 4476,-655.67 h60
  text ".VersionControl_RevNumber" at 4982,-655.67 h60
  text "LAYER NAME =" at -228.5,-858.49 h60
  text "TID #:" at 2248,-859 h60
  text ".TID" at 2793.5,-859 h60
  text "PLOT NAME =" at -228.5,-1064.34 h60
  text ".plot_File_Name" at 577,-1064.34 h60
  text "GENERATED    :" at 2250,-1064.34 h60
  text ".Print_Date" at 3119.5,-1064.34 h60
  text ".Print_Time" at 3848.5,-1064.34 h60
  text "TEXAS INSTRUMENTS" at 5113,-1064.34 h60
M12 Stackup:
  drawing of 191 lines, arcs and shapes, not listed
  text "Layer" at 9790.34,7830 h60
  text "Name" at 10200.26,7830 h60
  text "Material" at 11130,7830 h60
  text "Thickness" at 11989.77,7830 h60
  text "Constant" at 12639.6,7830 h60
  text "Board Layer Stack" at 13209.46,7830 h60
  text "1" at 9790.34,7710 h60
  text "Top Overlay" at 10200.26,7710 h60
  text "2" at 9790.34,7590 h60
  text "Top Solder" at 10200.26,7590 h60
  text "Solder Resist" at 11130,7590 h60
  text "0.40mil" at 11989.77,7590 h60
  text "3.5" at 12639.6,7590 h60
  text "3" at 9790.34,7470 h60
  text "Top Layer" at 10200.26,7470 h60
  text "Copper" at 11130,7470 h60
  text "1.40mil" at 11989.77,7470 h60
  text "4" at 9790.34,7350 h60
  text "Dielectric1" at 10200.26,7350 h60
  text "FR-4" at 11130,7350 h60
  text "59.20mil" at 11989.77,7350 h60
  text "4.8" at 12639.6,7350 h60
  text "5" at 9790.34,7230 h60
  text "Bottom Layer" at 10200.26,7230 h60
  text "Copper" at 11130,7230 h60
  text "1.40mil" at 11989.77,7230 h60
  text "6" at 9790.34,7110 h60
  text "Bottom Solder" at 10200.26,7110 h60
  text "Solder Resist" at 11130,7110 h60
  text "0.40mil" at 11989.77,7110 h60
  text "3.5" at 12639.6,7110 h60
  text "7" at 9790.34,6990 h60
  text "Bottom Overlay" at 10200.26,6990 h60
  text ".Layer_Name" at 577,-858.49 h60
M13 Component Bodies Top:
  text ".Layer_Name" at 577,-858.49 h60
M14 Component Bodies Bottom:
  text ".Layer_Name" at 577,-858.49 h60
M15 Courtyards Top:
  text ".Layer_Name" at 577,-858.49 h60
M16 Courtyards Bottom:
  text ".Layer_Name" at 577,-858.49 h60
Drill Drawing:
  circle w10: c5348.9,2909.61 r13.28
  circle w10: c5348.9,2909.61 r22.14
  circle w10: c5348.9,2311.88 r22.14
  lines w10: 5326.76,2234.39 5371.04,2234.39 5348.9,2190.12 5326.76,2234.39 ; 5326.76,2389.36 5371.04,2389.36 5371.04,2433.64 5326.76,2433.64 5326.76,2389.36 ; 5326.76,2488.98 5348.9,2500.05 5371.04,2488.98 5359.97,2511.12 5371.04,2533.26 5348.9,2522.19 5326.76,2533.26 5337.83,2511.12 5326.76,2488.98 ; 5326.76,2599.68 5337.83,2599.68 5348.9,2588.61 5359.97,2599.68 5371.04,2599.68 5359.97,2610.75 5371.04,2621.81 5359.97,2621.81 5348.9,2632.88 5337.83,2621.81 5326.76,2621.81 5337.83,2610.75 5326.76,2599.68 ; 5326.76,2732.51 5371.04,2732.51 5348.9,2688.23 5326.76,2732.51 ; 5326.76,2787.85 5371.04,2787.85 5371.04,2832.13 5326.76,2832.13 5326.76,2787.85 ; 5326.76,3009.23 5348.9,2987.1 5371.04,3009.23 5348.9,3031.37 5326.76,3009.23 ; 5326.76,3097.79 5337.83,3097.79 5337.83,3086.72 5359.97,3086.72 5359.97,3097.79 5371.04,3097.79 5371.04,3119.93 5359.97,3119.93 5359.97,3131 5337.83,3131 5337.83,3119.93 5326.76,3119.93 5326.76,3097.79 ; 5326.76,3186.34 5326.76,3197.41 5337.83,3208.48 5326.76,3219.55 5326.76,3230.62 5337.83,3230.62 5348.9,3219.55 5359.97,3230.62 5371.04,3230.62 5371.04,3219.55 5359.97,3208.48 5371.04,3197.41 5371.04,3186.34 5359.97,3186.34 5348.9,3197.41 5337.83,3186.34 5326.76,3186.34 ; 5326.76,3285.96 5348.9,3297.03 5371.04,3285.96 5359.97,3308.1 5371.04,3330.24 5348.9,3319.17 5326.76,3330.24 5337.83,3308.1 5326.76,3285.96 ; 5335.62,2497.84 5348.9,2504.48 5362.18,2497.84 5355.54,2511.12 5362.18,2524.41 5348.9,2517.76 5335.62,2524.41 5342.26,2511.12 5335.62,2497.84 ; 5335.62,2723.65 5362.18,2723.65 5348.9,2697.08 5335.62,2723.65 ; 5335.62,2796.71 5362.18,2796.71 5362.18,2823.27 5335.62,2823.27 5335.62,2796.71
  lines w12: 5286,2160.23 8398.94,2160.23 ; 5286,3355.7 8398.94,3355.7 ; 5601.63,2060.61 5601.63,3455.32 ; 5918.82,2060.61 5918.82,3455.32 ; 6540.56,2060.61 6540.56,3455.32 ; 6784.88,2060.61 6784.88,3455.32 ; 7145.22,2060.61 7145.22,3455.32 ; 7854.73,2060.61 7854.73,3455.32 ; 5286,2060.61 8398.94,2060.61 8398.94,3455.32 5286,3455.32 5286,2060.61
  text "Symbol" at 5345.77,3385.59 h72
  text "Quantity" at 5631.52,3385.59 h72
  text "Finished Hole Size" at 5948.7,3385.59 h72
  text "Plated" at 6570.45,3385.59 h72
  text "Hole Type" at 6814.77,3385.59 h72
  text "Drill Layer Pair" at 7175.11,3385.59 h72
  text "Hole Tolerance" at 7884.62,3385.59 h72
  text "4" at 5631.52,3285.96 h60
  text "7.87mil (0.200mm)" at 5948.7,3285.96 h60
  text "PTH" at 6570.45,3285.96 h60
  text "Round" at 6814.77,3285.96 h60
  text "Top Layer - Bottom Layer" at 7175.11,3285.96 h60
  text "7" at 5631.52,3186.34 h60
  text "12.00mil (0.305mm)" at 5948.7,3186.34 h60
  text "PTH" at 6570.45,3186.34 h60
  text "Round" at 6814.77,3186.34 h60
  text "Top Layer - Bottom Layer" at 7175.11,3186.34 h60
  text "1" at 5631.52,3086.72 h60
  text "16.00mil (0.406mm)" at 5948.7,3086.72 h60
  text "PTH" at 6570.45,3086.72 h60
  text "Round" at 6814.77,3086.72 h60
  text "Top Layer - Bottom Layer" at 7175.11,3086.72 h60
  text "2" at 5631.52,2987.1 h60
  text "23.00mil (0.584mm)" at 5948.7,2987.1 h60
  text "PTH" at 6570.45,2987.1 h60
  text "Round" at 6814.77,2987.1 h60
  text "Top Layer - Bottom Layer" at 7175.11,2987.1 h60
  text "9" at 5631.52,2887.47 h60
  text "24.00mil (0.610mm)" at 5948.7,2887.47 h60
  text "PTH" at 6570.45,2887.47 h60
  text "Round" at 6814.77,2887.47 h60
  text "Top Layer - Bottom Layer" at 7175.11,2887.47 h60
  text "11" at 5631.52,2787.85 h60
  text "28.00mil (0.711mm)" at 5948.7,2787.85 h60
  text "PTH" at 6570.45,2787.85 h60
  text "Round" at 6814.77,2787.85 h60
  text "Top Layer - Bottom Layer" at 7175.11,2787.85 h60
  text "3" at 5631.52,2688.23 h60
  text "32.00mil (0.813mm)" at 5948.7,2688.23 h60
  text "PTH" at 6570.45,2688.23 h60
  text "Round" at 6814.77,2688.23 h60
  text "Top Layer - Bottom Layer" at 7175.11,2688.23 h60
  text "2" at 5631.52,2588.61 h60
  text "33.46mil (0.850mm)" at 5948.7,2588.61 h60
  text "PTH" at 6570.45,2588.61 h60
  text "Round" at 6814.77,2588.61 h60
  text "Top Layer - Bottom Layer" at 7175.11,2588.61 h60
  text "10" at 5631.52,2488.98 h60
  text "45.00mil (1.143mm)" at 5948.7,2488.98 h60
  text "PTH" at 6570.45,2488.98 h60
  text "Round" at 6814.77,2488.98 h60
  text "Top Layer - Bottom Layer" at 7175.11,2488.98 h60
  text "7" at 5631.52,2389.36 h60
  text "45.28mil (1.150mm)" at 5948.7,2389.36 h60
  text "PTH" at 6570.45,2389.36 h60
  text "Round" at 6814.77,2389.36 h60
  text "Top Layer - Bottom Layer" at 7175.11,2389.36 h60
  text "4" at 5631.52,2289.74 h60
  text "125.98mil (3.200mm)" at 5948.7,2289.74 h60
  text "PTH" at 6570.45,2289.74 h60
  text "Round" at 6814.77,2289.74 h60
  text "Top Layer - Bottom Layer" at 7175.11,2289.74 h60
  text "2" at 5631.52,2190.12 h60
  text "31.50mil (0.800mm)" at 5948.7,2190.12 h60
  text "PTH" at 6570.45,2190.12 h60
  text "Slot" at 6814.77,2190.12 h60
  text "Top Layer - Bottom Layer" at 7175.11,2190.12 h60
  text "62 Total" at 5631.52,2090.5 h60
  text "Slot definitions :" at 5345.77,2010.88 h60
  text "Routed Path Length" at 5789.08,2010.88 h60
  text "= Calculated from tool start centre position to tool end centre position." at 6321.41,2010.88 h60
  text "Hole Length" at 5789.08,1961.15 h60
  text "= Routed Path Length + Tool Size = Slot length as defined in the PCB layout" at 6121.61,1961.15 h60
  text ".Layer_Name" at 577,-858.49 h60
M17 Embedded Cavity:
  text ".Layer_Name" at 577,-858.49 h60
M18 Embedded Assembly:
  text ".Layer_Name" at 577,-858.49 h60
M19 Embedded Keepout:
  text ".Layer_Name" at 577,-858.49 h60

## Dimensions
0,-400 to 1000,-400 on M2 Board Dimensions
0,0 to 0,1700 on M2 Board Dimensions
0,0 to 2500,0 on M2 Board Dimensions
